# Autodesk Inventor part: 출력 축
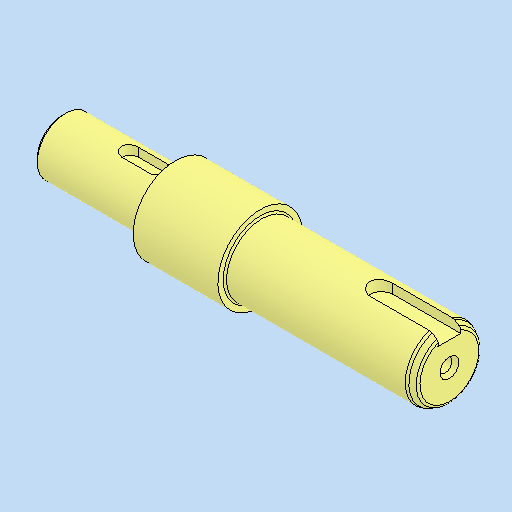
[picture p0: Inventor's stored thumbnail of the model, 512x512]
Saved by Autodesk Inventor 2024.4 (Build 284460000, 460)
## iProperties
Created: 2025-11
Part Number: 출력 축
Material: 강철, 탄소
Document SubType Name: Modeling
Designer: home
Density: 7.85 g/cm^3
Appearance: 기본값
Author: jhkim
Sending System: Autodesk Inventor 2026
Preprocessor: ST-DEVELOPER v20.1
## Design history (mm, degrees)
feature "솔리드1"
node "솔리드2"
